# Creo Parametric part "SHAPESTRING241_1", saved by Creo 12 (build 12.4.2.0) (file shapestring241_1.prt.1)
Units: Custom; MM, KILOGRAM, SECS

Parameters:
  PTC_WM_ITERATION = "0"
  PTC_WM_VERSION = "-.0"
  PTC_WM_LIFECYCLE_STATE = "In Work"
  PTC_WM_LIFECYCLE = "MO_CADDocument"
  PTC_WM_CREATED_BY = "Maximilian Roepper (Z0017RMS: MO)"
  PTC_WM_CREATED_ON = "18-Sep-26 11:36:42 AM"
  PTC_WM_MODIFIED_BY = "Maximilian Roepper (Z0017RMS: MO)"
  PTC_WM_MODIFIED_ON = "18-Sep-26 11:36:46 AM"
  PDMLINKNUMBER = "PDM000071454985"
  PTC_WM_NAME = "shapestring241_1.prt"
  PTC_WM_NUMBER = "PDM000071454985"

Other parameters: WEIGHT, WEIGHT_FACTOR, WEIGHT_ADD, _MASS_TEMP, _DIFF_TEMP, MC_ERRORS, SUPPLIER

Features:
  1. coordinate system
  2. datum plane "PRT_YZ"
  3. datum plane "PRT_XY"
  4. datum plane "PRT_XZ"
  5. coordinate system
  6. datum axis
  7. datum axis
  8. datum axis
  9. coordinate system
  10. imported feature
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
Other named items: PRT, SIEMENS_MO, DRW_VIEW_ORG, PRT_X, PRT_Y, PRT_Z, CS0, ROUGH_GROB

Layers: 00_STD_CSYS-KSYS, 01_STD_PLANES-EBENEN, 02_STD_AXES-ACHSEN, 03_STD_CSYS-KSYS, 24_IMPORT_FEAT-IMPORT_KE, INTFCLR

Surfaces: 1 plane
